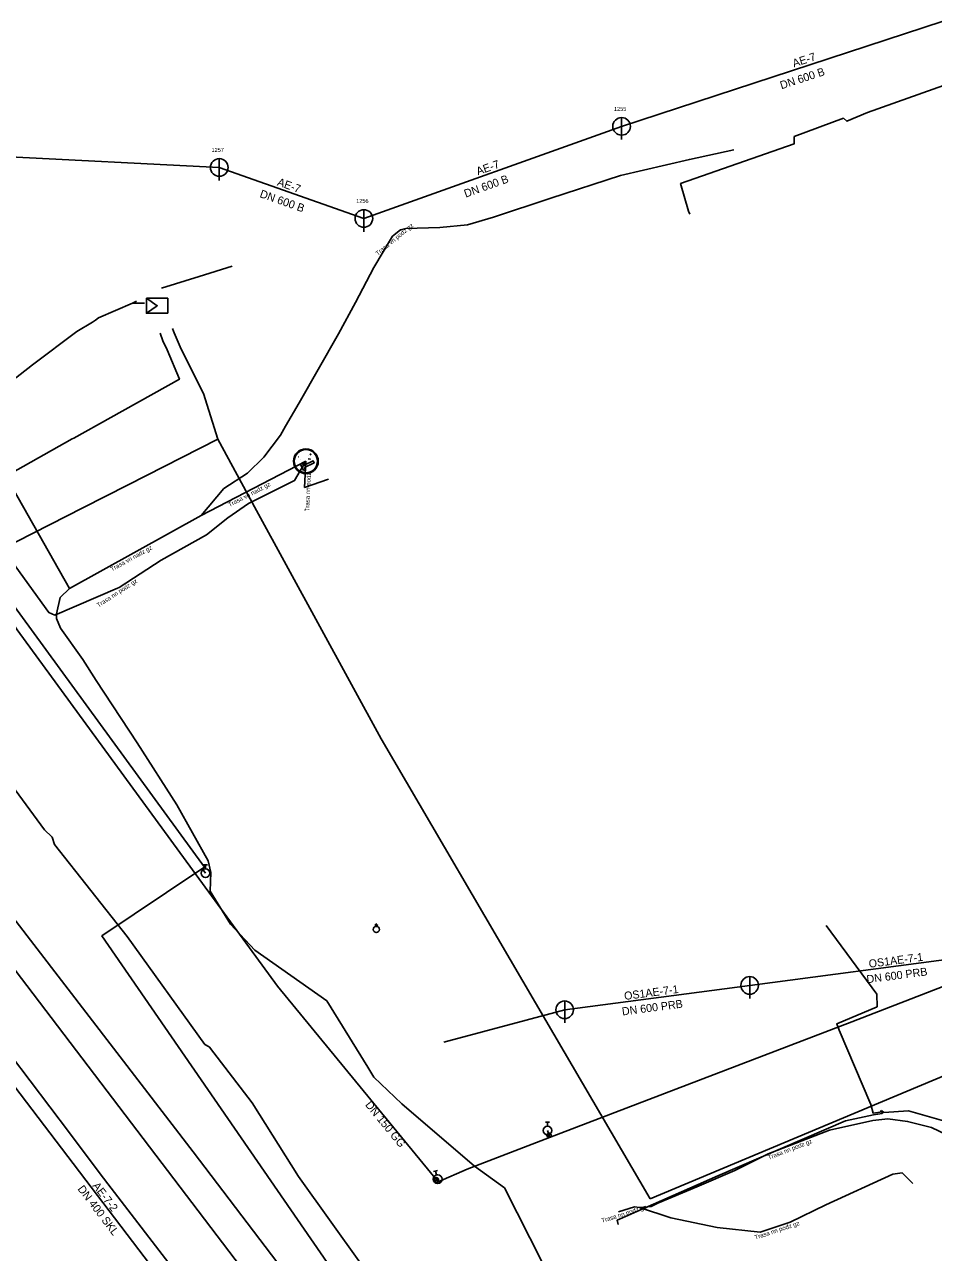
# Model space of a CAD drawing. Extents: x -493753 to -49291, y -1127285 to -112662.
# Drawn here: x -493415.3 to -493312, y -1127084.4 to -1126944.7 of the extents above; entities that cross this region are included whole.
import ezdxf

# ---------------------------------------------------------------- set-up
doc = ezdxf.new("R2010")
doc.units = 0
for name, color, linetype in [('Vrstva 1', 7, 'Continuous'), ('Vrstva 12', 7, 'Continuous'), ('Vrstva 15', 7, 'Continuous'), ('Vrstva 17', 7, 'Continuous'), ('Vrstva 19', 7, 'Continuous'), ('Vrstva 20', 7, 'Continuous'), ('Vrstva 22', 7, 'Continuous'), ('Vrstva 24', 7, 'Continuous'), ('Vrstva 25', 7, 'Continuous'), ('Vrstva 26', 7, 'Continuous'), ('Vrstva 3', 7, 'Continuous'), ('Vrstva 31', 7, 'Continuous'), ('Vrstva 39', 7, 'Continuous'), ('Vrstva 5', 7, 'Continuous'), ('Vrstva 6', 7, 'Continuous'), ('Vrstva 8', 7, 'Continuous'), ('Vrstva 9', 7, 'Continuous')]:
    doc.layers.add(name, color=color, linetype=linetype)

# ---------------------------------------------------------------- blocks, each defined once
blk = doc.blocks.new('_UZAVE')
at = {"layer": 'Vrstva 1'}
for p, q in [((-0.035, -0.035), (0.035, 0.035)), ((0.035, -0.035), (-0.035, 0.035))]:
    blk.add_line(p, q, dxfattribs=at)
for radius in [0.05, 0.0025]:
    blk.add_circle((0, 0), radius, dxfattribs=at)
blk = doc.blocks.new('_HYDRA')
at = {"layer": 'Vrstva 1'}
for p, q in [((-0.0225, 0.095), (0.0225, 0.095)), ((0, 0.095), (0, 0.05))]:
    blk.add_line(p, q, dxfattribs=at)
blk.add_circle((0, 0), 0.05, dxfattribs=at)
blk = doc.blocks.new('_SACHT')
at = {"layer": 'Vrstva 1'}
blk.add_line((0, 0.035), (0, 0.05), dxfattribs=at)
blk.add_lwpolyline([(-0.015, 0.05), (0, 0.065), (0.015, 0.05), (0.0025, 0.05)], close=True, dxfattribs=at)
blk.add_circle((0, 0), 0.035, dxfattribs=at)
blk = doc.blocks.new('_SACH0')
at = {"layer": 'Vrstva 1'}
blk.add_line((0, 0.05), (0, -0.075), dxfattribs=at)
blk.add_circle((0, 0), 0.05, dxfattribs=at)

msp = doc.modelspace()

# ---------------------------------------------------------------- linework, layer by layer
at = {"layer": 'Vrstva 1'}
for p, q in [((-493403.07, -1126976.4), (-493402.61, -1126976.2)), ((-493397.54, -1126981.65), (-493394.98, -1126986.7))]:
    msp.add_line(p, q, dxfattribs=at)
for points in [[(-493393.38, -1126991.88), (-493403.57, -1126997.06), (-493408.72, -1126999.68), (-493421.9, -1127006.38), (-493451.16, -1126957.48), (-493453.5, -1126951.96), (-493486.26, -1126874.64), (-493487, -1126872.89), (-493487.52, -1126871.61), (-493487.88, -1126870.61), (-493487.89, -1126870.58), (-493488.33, -1126869.34), (-493488.49, -1126868.9), (-493493.92, -1126853.77), (-493494.71, -1126851.57), (-493494.94, -1126850.93), (-493495.49, -1126849.33), (-493512.69, -1126802.2), (-493517.09, -1126789.79), (-493516.41, -1126786.25), (-493507.48, -1126781.99), (-493508.14, -1126780.34), (-493515.01, -1126760.11)], [(-493321.71, -1127171.3), (-493355.7, -1127126.12), (-493396.16, -1127072.91), (-493440.36, -1127015.46), (-493443.8, -1127011.63), (-493444.46, -1127010.85), (-493446.49, -1127008.27), (-493452.76, -1127000), (-493477.07, -1126967.92), (-493488.61, -1126953.19), (-493508.76, -1126886.04), (-493510.25, -1126878.84), (-493511.22, -1126875.6), (-493511.24, -1126875.56), (-493513.66, -1126867.49), (-493514.58, -1126864.18), (-493529.68, -1126809.77)], [(-493409.41, -1126979.62), (-493407.62, -1126978.58), (-493407.27, -1126978.34), (-493406.92, -1126978.1), (-493403.07, -1126976.4)], [(-493398.52, -1126979.31), (-493398.41, -1126979.59), (-493398.33, -1126979.77)], [(-493424.93, -1126991.62), (-493424.79, -1126991.51), (-493424.79, -1126991.51), (-493414.43, -1126983.43), (-493409.41, -1126979.62)], [(-493399.92, -1126979.84), (-493399.6, -1126980.68), (-493399.13, -1126981.72)], [(-493398.33, -1126979.77), (-493397.65, -1126981.37), (-493397.54, -1126981.65)], [(-493399.13, -1126981.72), (-493397.74, -1126985.07), (-493405.55, -1126989.43), (-493409.75, -1126991.76), (-493409.92, -1126991.86), (-493416.98, -1126995.83), (-493421.16, -1126998.21), (-493423.27, -1126999.39), (-493423.75, -1126999.78), (-493424.09, -1127000), (-493424.36, -1127000.17), (-493424.83, -1127000.44), (-493425.85, -1127001.15), (-493435.41, -1127006.98), (-493435.77, -1127007.13), (-493439.63, -1127009.05), (-493444.01, -1127010.71)], [(-493394.98, -1126986.7), (-493393.38, -1126991.88), (-493388.95, -1127000), (-493374.8, -1127025.95), (-493357.23, -1127055.99), (-493355.16, -1127059.53), (-493344.2, -1127078.27)], [(-493449.32, -1127009.16), (-493448.7, -1127009.96), (-493417.13, -1127051.31), (-493359.41, -1127127.23), (-493359.11, -1127127.63), (-493358.81, -1127128.03), (-493324.79, -1127172.89)], [(-493344.2, -1127078.27), (-493319.39, -1127067.89), (-493310.54, -1127064.17)]]:
    msp.add_lwpolyline(points, dxfattribs=at)
at = {"layer": 'Vrstva 12'}
for points in [[(-493423.69, -1127053.02), (-493410.22, -1127070.78), (-493406.86, -1127075.29), (-493405.87, -1127076.58)], [(-493405.87, -1127076.58), (-493390.1, -1127097.09), (-493379.29, -1127111.66), (-493373.09, -1127118.86), (-493358.81, -1127137.57), (-493338.23, -1127165.37), (-493330.73, -1127175.97)]]:
    msp.add_lwpolyline(points, dxfattribs=at)
at = {"layer": 'Vrstva 15'}
for p, q in [((-493347.44, -1126956.31), (-493304.79, -1126942.33)), ((-493376.75, -1126966.79), (-493347.44, -1126956.31)), ((-493445.06, -1126958.36), (-493393.2, -1126960.98)), ((-493393.2, -1126960.98), (-493376.75, -1126966.79)), ((-493332.87, -1127054), (-493301.04, -1127049.81)), ((-493353.91, -1127056.77), (-493332.87, -1127054)), ((-493353.91, -1127056.77), (-493367.65, -1127060.44)), ((-493389.89, -1127100.39), (-493422.05, -1127058.22))]:
    msp.add_line(p, q, dxfattribs=at)
at = {"layer": 'Vrstva 20'}
for p, q in [((-493395.14, -1127040.71), (-493394.77, -1127041.23)), ((-493368.5, -1127076.11), (-493368.36, -1127076.03))]:
    msp.add_line(p, q, dxfattribs=at)
for points in [[(-493298.48, -1127056.18), (-493300.31, -1127050.04), (-493321.24, -1127058.14), (-493355.65, -1127071.3), (-493365, -1127074.9), (-493368.31, -1127076.35), (-493386.57, -1127054.09), (-493416.18, -1127013.57), (-493425.33, -1127000), (-493450.1, -1126961.95), (-493457.06, -1126948.64)], [(-493418.86, -1127007.7), (-493394.88, -1127040.54), (-493395.54, -1127040.98)], [(-493395.54, -1127040.98), (-493406.55, -1127048.37), (-493358.69, -1127117.78), (-493342.63, -1127139.58), (-493321.11, -1127170.99)], [(-493355.87, -1127070.5), (-493355.69, -1127071.04), (-493355.65, -1127071.3)]]:
    msp.add_lwpolyline(points, dxfattribs=at)
at = {"layer": 'Vrstva 25'}
for points in [[(-493324.19, -1127047.17), (-493318.39, -1127055), (-493318.38, -1127056.42), (-493322.97, -1127058.36), (-493322.7, -1127059.09), (-493319.08, -1127067.56), (-493318.83, -1127068.52), (-493318.04, -1127068.41), (-493317.86, -1127068.21)], [(-493291.4, -1127057.09), (-493291.65, -1127056.73), (-493293.68, -1127058.08), (-493295.94, -1127060.63), (-493297.56, -1127063.66), (-493298.37, -1127066.35), (-493298.73, -1127066.66), (-493307.14, -1127071.12), (-493307.61, -1127071.44), (-493310.84, -1127069.4), (-493314.8, -1127068.28), (-493317.63, -1127068.47), (-493317.86, -1127068.21)], [(-493347.82, -1127081.18), (-493347.93, -1127080.7), (-493336.49, -1127075.65), (-493321.97, -1127069.41), (-493318.79, -1127068.72), (-493317.82, -1127068.58), (-493317.86, -1127068.21)]]:
    msp.add_lwpolyline(points, dxfattribs=at)
at = {"layer": 'Vrstva 26'}
for p, q in [((-493419.87, -1127027.05), (-493413.09, -1127036.31)), ((-493413.09, -1127036.31), (-493412.24, -1127037.09)), ((-493412.24, -1127037.09), (-493412.2, -1127037.13)), ((-493412.2, -1127037.13), (-493411.93, -1127037.97)), ((-493411.93, -1127037.97), (-493403.69, -1127048.42)), ((-493403.69, -1127048.42), (-493394.84, -1127060.72)), ((-493394.84, -1127060.72), (-493394.34, -1127060.98)), ((-493394.34, -1127060.98), (-493394.31, -1127061.04)), ((-493394.31, -1127061.04), (-493389.45, -1127067.37)), ((-493389.45, -1127067.37), (-493384.18, -1127075.72)), ((-493384.18, -1127075.72), (-493376.93, -1127085.87))]:
    msp.add_line(p, q, dxfattribs=at)
at = {"layer": 'Vrstva 3'}
msp.add_line((-493403.07, -1126976.4), (-493401.72, -1126976.42), dxfattribs=at)
msp.add_lwpolyline([(-493399.77, -1126974.7), (-493395.5, -1126973.39), (-493391.72, -1126972.2)], dxfattribs=at)
at = {"layer": 'Vrstva 31'}
for p, q in [((-493401.49, -1126975.83), (-493399.04, -1126975.83)), ((-493399.04, -1126975.83), (-493399.04, -1126977.57)), ((-493399.04, -1126977.57), (-493401.49, -1126977.57))]:
    msp.add_line(p, q, dxfattribs=at)
msp.add_lwpolyline([(-493401.49, -1126975.83), (-493400.26, -1126976.7), (-493401.49, -1126977.57)], close=True, dxfattribs=at)
at = {"layer": 'Vrstva 39'}
for points in [[(-493235.73, -1127025.17), (-493236.53, -1127025.12), (-493241.4, -1127025.09), (-493243.79, -1127024), (-493248.52, -1127013.69), (-493250.11, -1127006.96), (-493251.66, -1127001.72), (-493252.99, -1126995.77), (-493253.77, -1126987.81), (-493254.97, -1126977.02), (-493255.48, -1126962.33), (-493256.31, -1126954.12), (-493256.68, -1126945.15), (-493257.3, -1126943.45), (-493260.26, -1126941.69), (-493266.63, -1126938.06), (-493269.86, -1126938.09), (-493289.32, -1126944.6), (-493307.43, -1126950.45), (-493319.46, -1126954.73), (-493321.82, -1126955.73), (-493322.21, -1126955.38)], [(-493327.81, -1126957.45), (-493322.21, -1126955.38)], [(-493327.81, -1126957.45), (-493327.81, -1126958.29), (-493340.73, -1126962.82), (-493339.84, -1126965.94), (-493339.69, -1126966.28)]]:
    msp.add_lwpolyline(points, dxfattribs=at)
at = {"layer": 'Vrstva 5'}
for points in [[(-493421.81, -1126997.49), (-493421.34, -1126998.22), (-493416.82, -1127005.7), (-493412.6, -1127011.6), (-493411.92, -1127011.88), (-493404.79, -1127008.83), (-493404.58, -1127008.74), (-493399.79, -1127005.63), (-493394.67, -1127002.77), (-493392.24, -1127000.82), (-493389.87, -1126999.21), (-493384.64, -1126996.59), (-493383.35, -1126994.39)], [(-493383.35, -1126994.39), (-493383.5, -1126997.37), (-493380.77, -1126996.44)], [(-493309.42, -1127071.48), (-493312.18, -1127070.17), (-493314.91, -1127069.46), (-493317.14, -1127069.17), (-493318.88, -1127069.38), (-493323.79, -1127070.46), (-493330.76, -1127073.17), (-493334.55, -1127075.03), (-493338.89, -1127076.91), (-493343.3, -1127078.76), (-493344.09, -1127079.15), (-493345.41, -1127079.25)], [(-493345.41, -1127079.25), (-493341.85, -1127080.42), (-493336.55, -1127081.53), (-493331.69, -1127082.06), (-493328.27, -1127080.92), (-493324.22, -1127078.95), (-493316.6, -1127075.46), (-493315.54, -1127075.3), (-493314.3, -1127076.52)], [(-493345.41, -1127079.25), (-493345.96, -1127079.17), (-493347.78, -1127079.74)]]:
    msp.add_lwpolyline(points, dxfattribs=at)
at = {"layer": 'Vrstva 6'}
for points in [[(-493410.24, -1127008.87), (-493452.6, -1126934.12)], [(-493395.27, -1127000.55), (-493392.67, -1126997.5), (-493389.99, -1126995.74), (-493388.12, -1126993.93), (-493386.23, -1126991.42), (-493385.66, -1126990.42), (-493384.13, -1126987.74), (-493379.65, -1126979.89), (-493377.71, -1126976.34), (-493375.61, -1126972.34), (-493373.49, -1126968.81), (-493372.58, -1126968.06), (-493371.97, -1126967.94), (-493368.13, -1126967.82), (-493364.97, -1126967.5), (-493362.01, -1126966.64), (-493355.5, -1126964.47), (-493347.58, -1126961.91), (-493339.72, -1126960.07), (-493334.66, -1126958.98)], [(-493395.27, -1127000.55), (-493383.35, -1126994.39)], [(-493410.24, -1127008.87), (-493395.27, -1127000.55)], [(-493356.45, -1127085.56), (-493360.77, -1127077.02), (-493364.17, -1127074.56), (-493372.45, -1127067.45), (-493375.62, -1127064.43), (-493376.32, -1127063.3), (-493380.98, -1127055.77), (-493389.14, -1127049.98), (-493391.93, -1127047.02), (-493394.25, -1127043.28), (-493394.16, -1127041.16), (-493394.47, -1127039.85), (-493398.04, -1127033.45), (-493402.54, -1127026.41), (-493407.19, -1127019.31), (-493408.71, -1127016.94), (-493411.24, -1127013.36), (-493411.73, -1127012.27), (-493411.7, -1127011.75), (-493411.29, -1127009.89), (-493410.24, -1127008.87)]]:
    msp.add_lwpolyline(points, dxfattribs=at)
at = {"layer": 'Vrstva 8'}
for points in [[(-493384.2, -1126993.9), (-493384.21, -1126993.9)], [(-493384, -1126994.16), (-493384, -1126994.16)], [(-493383.07, -1126994.1), (-493382.85, -1126994.16), (-493382.84, -1126994.16)], [(-493383.03, -1126993.76), (-493383.02, -1126993.77)], [(-493382.78, -1126993.71), (-493382.84, -1126993.59), (-493382.89, -1126993.53)]]:
    msp.add_lwpolyline(points, dxfattribs=at)
msp.add_lwpolyline([(-493383.61, -1126995.46), (-493383.96, -1126994.73), (-493383.74, -1126994.62), (-493383.63, -1126994.87), (-493382.52, -1126994.33), (-493382.4, -1126994.57), (-493383.51, -1126995.1), (-493383.39, -1126995.35)], close=True, dxfattribs=at)
for radius in [1.41, 1.32]:
    msp.add_circle((-493383.35, -1126994.39), radius, dxfattribs=at)

# ---------------------------------------------------------------- block references
at = {"layer": 'Vrstva 17'}
for name, p, xscale, yscale in [('_SACH0', (-493347.44, -1126956.31), 19.997500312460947, 19.997500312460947), ('_SACH0', (-493393.2, -1126960.98), 19.997500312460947, 19.997500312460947), ('_SACH0', (-493376.75, -1126966.79), 19.997500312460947, 19.997500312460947), ('_SACHT', (-493375.34, -1127047.64), 9.998750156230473, 9.998750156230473), ('_SACH0', (-493332.87, -1127054), 19.997500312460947, 19.997500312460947), ('_SACH0', (-493353.91, -1127056.77), 19.997500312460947, 19.997500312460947)]:
    msp.add_blockref(name, p, dxfattribs=dict(at, xscale=xscale, yscale=yscale))
at = {"layer": 'Vrstva 22'}
for name, p, xscale, yscale in [('_HYDRA', (-493394.77, -1127041.23), 9.998750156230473, 9.998750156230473), ('_HYDRA', (-493355.87, -1127070.5), 9.998750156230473, 9.998750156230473), ('_UZAVE', (-493355.69, -1127071.04), 4.999375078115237, 4.999375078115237)]:
    msp.add_blockref(name, p, dxfattribs=dict(at, xscale=xscale, yscale=yscale))
for name, p, xscale, yscale, rotation in [('_HYDRA', (-493368.36, -1127076.03), 9.998750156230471, 9.998750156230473, 15.146829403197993), ('_UZAVE', (-493368.5, -1127076.11), 4.999375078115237, 4.999375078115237, 90)]:
    msp.add_blockref(name, p, dxfattribs=dict(at, xscale=xscale, yscale=yscale, rotation=rotation))

# ---------------------------------------------------------------- texts
at = {"layer": 'Vrstva 19'}
for s, rotation, p in [('AE-7', 18.1596, (-493327.83, -1126949.6)), ('DN 600 B', 18.1596, (-493329.25, -1126952.1)), ('AE-7', 19.6613, (-493363.78, -1126961.88)), ('AE-7', 340.5481, (-493386.68, -1126963)), ('DN 600 B', 19.6613, (-493365.17, -1126964.42)), ('DN 600 B', 340.5481, (-493388.67, -1126964.34)), ('OS1AE-7-1', 7.4992, (-493319.27, -1127052)), ('DN 600 PRB', 7.4992, (-493319.52, -1127053.76)), ('OS1AE-7-1', 7.4992, (-493347.09, -1127055.66)), ('DN 600 PRB', 7.4992, (-493347.34, -1127057.42)), ('DN 400 SKL', 307.3305, (-493409.36, -1127077.16)), ('AE-7-2', 307.3305, (-493407.67, -1127076.8))]:
    msp.add_text(s, height=0.91, rotation=rotation, dxfattribs=at).set_placement(p)
for s, p in [('1255', (-493348.3, -1126954.55)), ('1257', (-493394.07, -1126959.21)), ('1256', (-493377.62, -1126965.02))]:
    msp.add_text(s, height=0.455, dxfattribs=at).set_placement(p)
at = {"layer": 'Vrstva 24'}
msp.add_text('DN 150 GG', height=0.91, rotation=309.3722, dxfattribs=at).set_placement((-493376.66, -1127067.61))
at = {"layer": 'Vrstva 9'}
for s, rotation, p in [('Trasa vn podz gz', 39.4945, (-493375.17, -1126971.03)), ('Trasa nn podz', 87.2065, (-493382.98, -1127000.1)), ('Trasa vn nadz gz', 27.3411, (-493392.02, -1126999.6)), ('Trasa vn nadz gz', 29.0562, (-493405.4, -1127006.93)), ('Trasa nn podz gz', 32.9944, (-493406.93, -1127011.03)), ('Trasa nn podz gz', 21.2795, (-493330.69, -1127073.84)), ('Trasa nn podz gz', 17.3956, (-493349.65, -1127081.01)), ('Trasa nn podz gz', 18.2792, (-493332.22, -1127082.92))]:
    msp.add_text(s, height=0.5, rotation=rotation, dxfattribs=at).set_placement(p)

doc.saveas('drawing.dxf')
